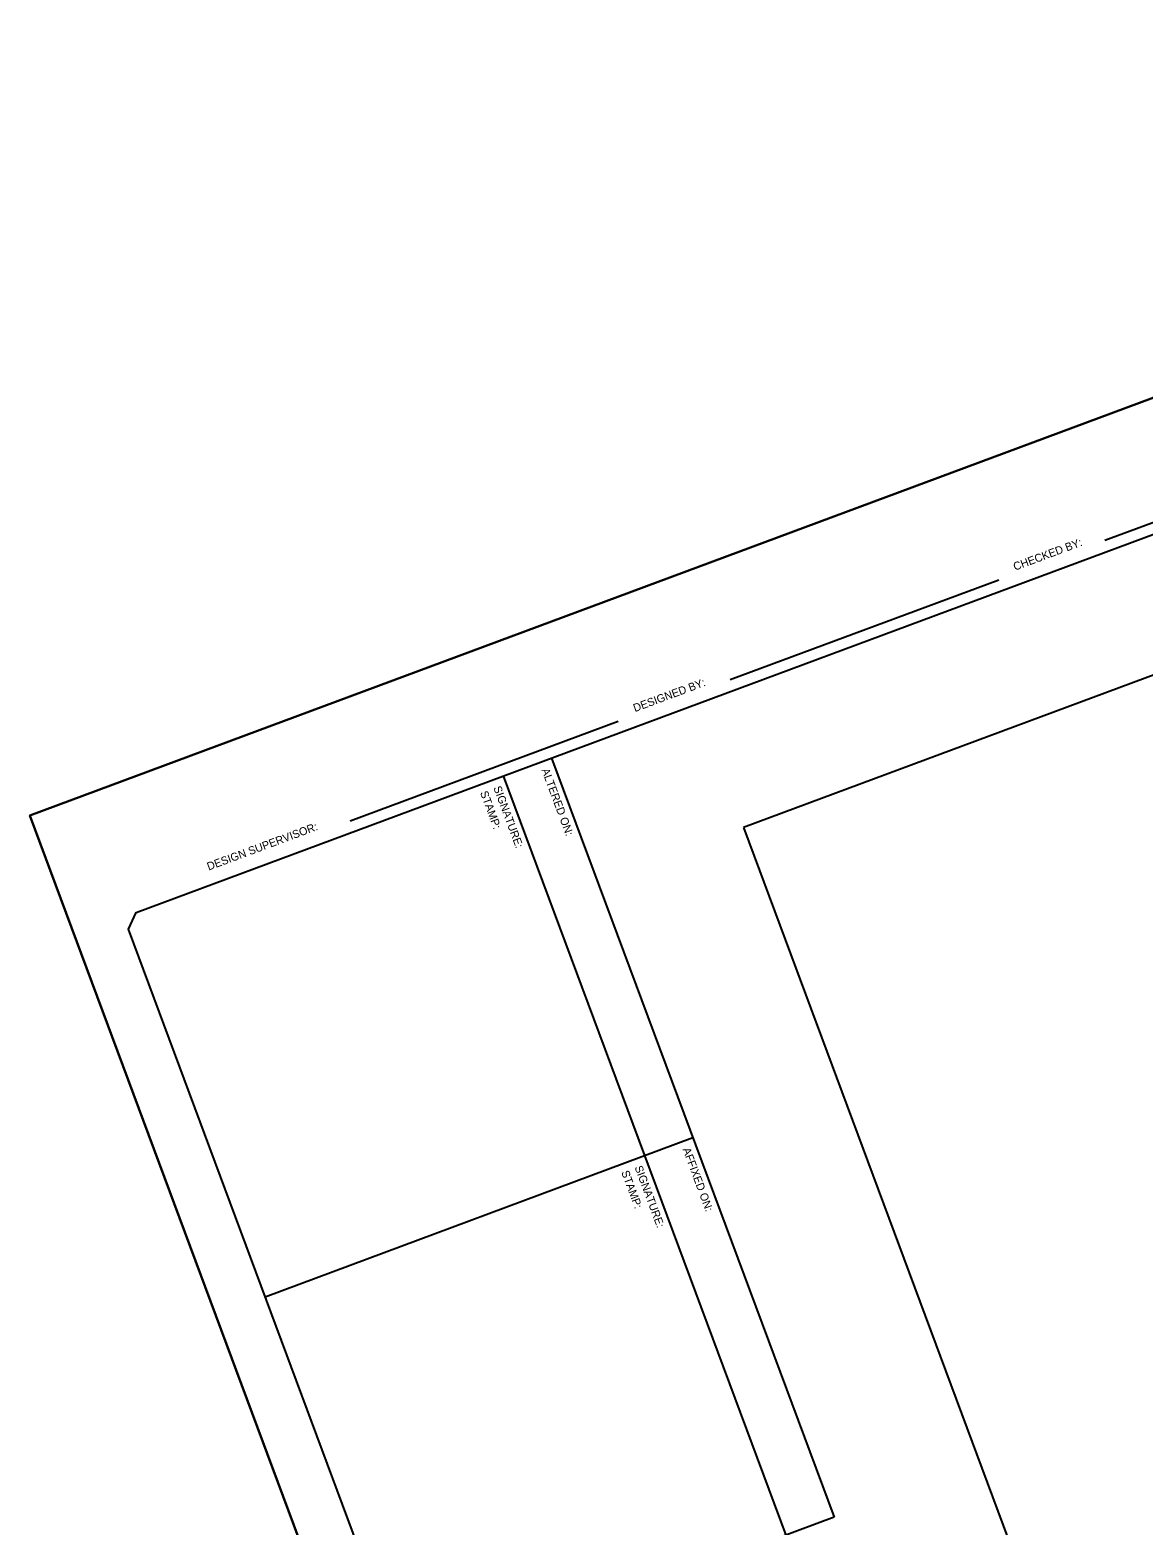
# Model space of a CAD drawing. Extents: x 1040172 to 1040822, y 1127790 to 1128580.
# Drawn here: x 1040172.1 to 1040389.4, y 1128288.4 to 1128580.3 of the extents above; entities that cross this region are included whole.
import ezdxf

# ---------------------------------------------------------------- set-up
doc = ezdxf.new("R2010")
doc.units = 0
for name, color, linetype in [('clip boundary', 7, 'Continuous'), ('SHEET_BORDER', 7, 'Continuous'), ('SHEET_BORDER_CUT', 7, 'Continuous'), ('SHEET_BORDER_STAMPBOX', 7, 'Continuous'), ('SHEET_BORDER_TEXT', 7, 'Continuous')]:
    doc.layers.add(name, color=color, linetype=linetype)

msp = doc.modelspace()

# ---------------------------------------------------------------- linework, layer by layer
at = {"layer": 'clip boundary'}
for points in [[(1040584.48, 1128580.33), (1040821.52, 1127942.99), (1040409.12, 1127789.61), (1040172.08, 1128426.95)], [(1040311.42, 1128424.61), (1040504.79, 1127904.67), (1040760.34, 1127999.71), (1040566.96, 1128519.66)]]:
    msp.add_lwpolyline(points, close=True, dxfattribs=at)
at = {"layer": 'SHEET_BORDER'}
for p, q in [((1040381.96, 1128480.72), (1040434.37, 1128500.21)), ((1040308.8, 1128453.51), (1040361.21, 1128473)), ((1040234.59, 1128425.91), (1040286.94, 1128445.38))]:
    msp.add_line(p, q, dxfattribs=at)
msp.add_lwpolyline([(1040412.42, 1127817.51), (1040409.2, 1127818.98), (1040191.33, 1128404.77), (1040192.81, 1128407.99), (1040581.19, 1128552.44), (1040584.4, 1128550.96), (1040802.27, 1127965.17), (1040800.8, 1127961.95)], close=True, dxfattribs=at)
at = {"layer": 'SHEET_BORDER_CUT'}
msp.add_lwpolyline([(1040172.08, 1128426.95), (1040409.12, 1127789.61), (1040821.52, 1127942.99), (1040584.48, 1128580.33)], close=True, dxfattribs=at)
msp.add_lwpolyline([(1040174.55, 1128420.33), (1040172.08, 1128426.95), (1040178.71, 1128429.42)], dxfattribs=at)
at = {"layer": 'SHEET_BORDER_STAMPBOX'}
for p, q in [((1040273.94, 1128438.16), (1040329.06, 1128289.96)), ((1040319.69, 1128286.47), (1040264.57, 1128434.68)), ((1040218.02, 1128333.01), (1040301.5, 1128364.06)), ((1040329.06, 1128289.96), (1040245.58, 1128258.91))]:
    msp.add_line(p, q, dxfattribs=at)

# ---------------------------------------------------------------- texts
for s, height, p in [('ALTERED ON:', 1.5625, (1040271.92, 1128435.87)), ('SIGNATURE:', 1.562, (1040262.54, 1128432.39)), ('STAMP:', 1.562, (1040259.94, 1128431.42)), ('AFFIXED ON:', 1.5625, (1040299.48, 1128361.77)), ('STAMP:', 1.562, (1040287.5, 1128357.32)), ('SIGNATURE:', 1.562, (1040290.1, 1128358.28))]:
    msp.add_text(s, height=height, rotation=290.4011, dxfattribs=at).set_placement(p)
at = {"layer": 'SHEET_BORDER_TEXT'}
for s, p in [('CHECKED BY:', (1040364.4, 1128474.74)), ('DESIGNED BY:', (1040290.2, 1128447.14)), ('DESIGN SUPERVISOR:', (1040206.99, 1128416.2))]:
    msp.add_text(s, height=1.5625, rotation=20.4011, dxfattribs=at).set_placement(p)

doc.saveas('drawing.dxf')
